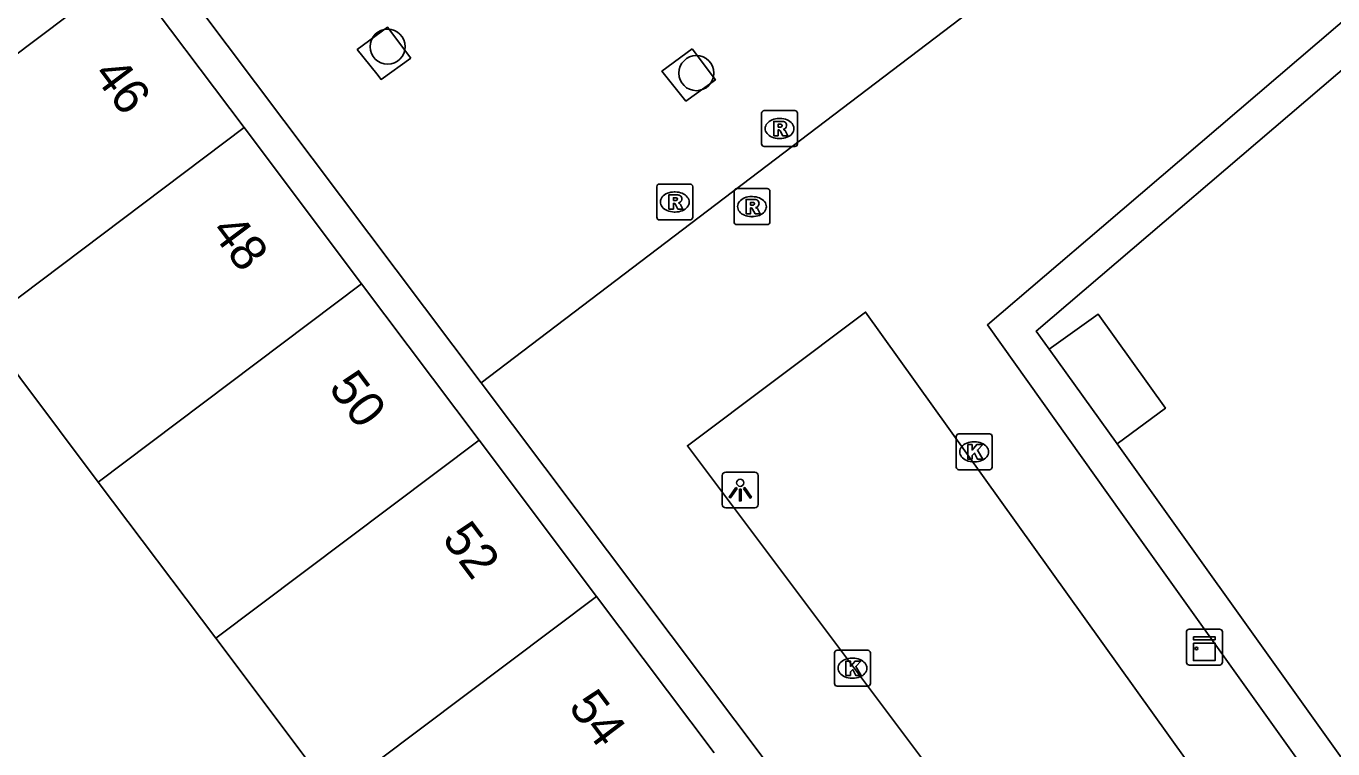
# Model space of a CAD drawing. Extents: x 160379 to 161131, y 383940 to 384849.
# Drawn here: x 160622.08 to 160658.49, y 384575.16 to 384595.29 of the extents above; entities that cross this region are included whole.
import ezdxf

# ---------------------------------------------------------------- set-up
doc = ezdxf.new("R2010")
doc.units = 0
for name, color, linetype in [('IMGEO_Boom', 7, 'Continuous'), ('IMGEO_Kast', 7, 'Continuous'), ('IMGEO_Kolk', 7, 'Continuous'), ('IMGEO_Lichtpunt', 7, 'Continuous'), ('IMGEO_Pand', 7, 'Continuous'), ('IMGEO_Pand_nummerreeks', 7, 'Continuous'), ('IMGEO_Pand_overbouw', 7, 'Continuous'), ('IMGEO_Rioolput', 7, 'Continuous'), ('IMGEO_Voetgangersgebied_open', 7, 'Continuous')]:
    doc.layers.add(name, color=color, linetype=linetype)

msp = doc.modelspace()

# ---------------------------------------------------------------- linework, layer by layer
at = {"layer": 'IMGEO_Boom'}
for centre in [(160632.154, 384594.722), (160640.758, 384593.985)]:
    msp.add_circle(centre, 0.489, dxfattribs=at)
at = {"layer": 'IMGEO_Kast'}
for p, q in [((160654.485, 384578.496), (160655.326, 384578.496)), ((160655.326, 384578.496), (160654.485, 384578.496)), ((160654.41, 384577.571), (160654.41, 384578.412)), ((160654.41, 384578.412), (160654.41, 384577.571)), ((160655.41, 384578.421), (160655.41, 384577.58)), ((160655.41, 384577.58), (160655.41, 384578.421)), ((160655.335, 384577.496), (160654.494, 384577.496)), ((160654.494, 384577.496), (160655.335, 384577.496))]:
    msp.add_line(p, q, dxfattribs=at)
for points in [[(160654.605, 384578.286), (160655.205, 384578.286), (160655.205, 384578.201), (160654.605, 384578.201), (160654.605, 384578.286)], [(160654.605, 384578.111), (160655.205, 384578.111), (160655.205, 384577.622), (160654.605, 384577.622), (160654.605, 384578.111)]]:
    msp.add_lwpolyline(points, dxfattribs=at)
msp.add_circle((160654.689, 384577.96), 0.0377, dxfattribs=at)
for centre, start, end in [((160654.488, 384578.418), 92.4484, 184.2845), ((160654.488, 384578.418), 92.4484, 184.2845), ((160655.332, 384578.418), 2.4484, 94.2845), ((160655.332, 384578.418), 2.4484, 94.2845), ((160654.488, 384577.574), 182.4484, 274.2845), ((160654.488, 384577.574), 182.4484, 274.2845), ((160655.332, 384577.574), 272.4484, 4.2845), ((160655.332, 384577.574), 272.4484, 4.2845)]:
    msp.add_arc(centre, 0.0779, start, end, dxfattribs=at)
at = {"layer": 'IMGEO_Kolk'}
for p, q in [((160647.995, 384583.011), (160647.995, 384583.863)), ((160648.07, 384583.937), (160648.922, 384583.937)), ((160648.483, 384583.717), (160648.508, 384583.717)), ((160648.996, 384583.863), (160648.996, 384583.011)), ((160648.922, 384582.937), (160648.07, 384582.937)), ((160648.506, 384583.157), (160648.481, 384583.157)), ((160644.604, 384576.984), (160644.604, 384577.836)), ((160644.679, 384577.91), (160645.531, 384577.91)), ((160645.605, 384577.836), (160645.605, 384576.984)), ((160645.092, 384577.69), (160645.117, 384577.69)), ((160645.115, 384577.13), (160645.09, 384577.13)), ((160645.531, 384576.91), (160644.679, 384576.91))]:
    msp.add_line(p, q, dxfattribs=at)
for points in [[(160647.995, 384583.011), (160647.995, 384583.863)], [(160648.07, 384583.937), (160648.922, 384583.937)], [(160648.316, 384583.637), (160648.439, 384583.637), (160648.439, 384583.486), (160648.569, 384583.637), (160648.733, 384583.637), (160648.587, 384583.486), (160648.74, 384583.237), (160648.588, 384583.237), (160648.503, 384583.401), (160648.439, 384583.334), (160648.439, 384583.237), (160648.316, 384583.237), (160648.316, 384583.637)], [(160648.996, 384583.863), (160648.996, 384583.011)], [(160648.922, 384582.937), (160648.07, 384582.937)], [(160644.604, 384576.984), (160644.604, 384577.836)], [(160644.679, 384577.91), (160645.531, 384577.91)], [(160645.605, 384577.836), (160645.605, 384576.984)], [(160644.925, 384577.61), (160645.048, 384577.61), (160645.048, 384577.459), (160645.178, 384577.61), (160645.342, 384577.61), (160645.196, 384577.459), (160645.349, 384577.21), (160645.197, 384577.21), (160645.112, 384577.374), (160645.048, 384577.307), (160645.048, 384577.21), (160644.925, 384577.21), (160644.925, 384577.61)], [(160645.531, 384576.91), (160644.679, 384576.91)]]:
    msp.add_lwpolyline(points, dxfattribs=at)
for centre, start, end in [((160648.072, 384583.861), 91.552, 178.448), ((160648.072, 384583.861), 91.552, 178.448), ((160648.92, 384583.861), 1.552, 88.448), ((160648.92, 384583.861), 1.552, 88.448), ((160648.072, 384583.013), 181.552, 268.448), ((160648.072, 384583.013), 181.552, 268.448), ((160648.92, 384583.013), 271.552, 358.448), ((160648.92, 384583.013), 271.552, 358.448), ((160644.681, 384577.834), 91.552, 178.448), ((160644.681, 384577.834), 91.552, 178.448), ((160645.529, 384577.834), 1.552, 88.448), ((160645.529, 384577.834), 1.552, 88.448), ((160644.681, 384576.986), 181.552, 268.448), ((160644.681, 384576.986), 181.552, 268.448), ((160645.529, 384576.986), 271.552, 358.448), ((160645.529, 384576.986), 271.552, 358.448)]:
    msp.add_arc(centre, 0.0765, start, end, dxfattribs=at)
for centre, major_axis, ratio, start_param, end_param in [((160648.482, 384583.437), (-0.387, 0.002), 0.722429, 4.712389, 7.853982), ((160648.507, 384583.437), (-0.39, 0.002), 0.717154, 1.570796, 4.712389), ((160645.091, 384577.41), (-0.387, 0.002), 0.722429, 4.712389, 7.853982), ((160645.116, 384577.41), (-0.39, 0.002), 0.717154, 1.570796, 4.712389)]:
    msp.add_ellipse(centre, major_axis=major_axis, ratio=ratio, start_param=start_param, end_param=end_param, dxfattribs=at)
at = {"layer": 'IMGEO_Lichtpunt'}
for p, q in [((160642.381, 384582.872), (160641.573, 384582.872)), ((160642.381, 384582.872), (160641.573, 384582.872)), ((160641.479, 384582.777), (160641.479, 384581.97)), ((160641.479, 384582.777), (160641.479, 384581.97)), ((160642.475, 384581.97), (160642.475, 384582.777)), ((160642.475, 384581.97), (160642.475, 384582.777)), ((160641.573, 384581.876), (160642.381, 384581.876)), ((160641.573, 384581.876), (160642.381, 384581.876))]:
    msp.add_line(p, q, dxfattribs=at)
for points in [[(160641.853, 384582.441), (160641.892, 384582.413), (160641.704, 384582.151), (160641.666, 384582.178), (160641.853, 384582.441)], [(160641.955, 384582.393), (160642.002, 384582.393), (160642.002, 384582.071), (160641.955, 384582.071), (160641.955, 384582.393)], [(160642.065, 384582.413), (160642.103, 384582.44), (160642.29, 384582.178), (160642.251, 384582.15), (160642.065, 384582.413)]]:
    msp.add_lwpolyline(points, dxfattribs=at)
msp.add_circle((160641.978, 384582.575), 0.0994, dxfattribs=at)
for centre, start, end in [((160641.573, 384582.777), 90, 180), ((160641.573, 384582.777), 90, 180), ((160642.381, 384582.777), 0, 90), ((160642.381, 384582.777), 0, 90), ((160641.573, 384581.97), 180, 270), ((160641.573, 384581.97), 180, 270), ((160642.381, 384581.97), 270, 0), ((160642.381, 384581.97), 270, 360)]:
    msp.add_arc(centre, 0.0946, start, end, dxfattribs=at)
at = {"layer": 'IMGEO_Pand'}
for points in [[(160663.725, 384567.919), (160652.479, 384583.658), (160653.822, 384584.649), (160651.953, 384587.271), (160650.586, 384586.297), (160650.225, 384586.801), (160659.075, 384594.356), (160663.636, 384598.249), (160664.714, 384596.986), (160667.165, 384599.079), (160666.087, 384600.341), (160670.751, 384604.318), (160692.141, 384590.55)], [(160624.884, 384596.822), (160617.544, 384591.3)], [(160624.884, 384596.822), (160628.157, 384592.469)], [(160628.157, 384592.469), (160620.818, 384586.948)], [(160628.157, 384592.469), (160631.431, 384588.116)], [(160631.431, 384588.116), (160624.091, 384582.595)], [(160631.431, 384588.116), (160634.704, 384583.762)], [(160624.091, 384582.595), (160620.818, 384586.948)], [(160634.704, 384583.762), (160627.365, 384578.243)], [(160634.704, 384583.762), (160637.977, 384579.409)], [(160627.365, 384578.243), (160624.091, 384582.595)], [(160637.977, 384579.409), (160630.639, 384573.89)], [(160637.977, 384579.409), (160641.25, 384575.056)], [(160630.639, 384573.89), (160627.365, 384578.243)]]:
    msp.add_lwpolyline(points, dxfattribs=at)
at = {"layer": 'IMGEO_Pand_overbouw'}
msp.add_lwpolyline([(160652.479, 384583.658), (160653.822, 384584.649), (160651.953, 384587.271), (160650.586, 384586.297)], close=True, dxfattribs=at)
at = {"layer": 'IMGEO_Rioolput'}
for p, q in [((160642.574, 384592.016), (160642.574, 384592.868)), ((160642.649, 384592.942), (160643.501, 384592.942)), ((160643.062, 384592.722), (160643.087, 384592.722)), ((160643.575, 384592.868), (160643.575, 384592.016)), ((160643.085, 384592.162), (160643.06, 384592.162)), ((160643.501, 384591.942), (160642.649, 384591.942)), ((160639.729, 384590.896), (160640.581, 384590.896)), ((160639.654, 384589.97), (160639.654, 384590.822)), ((160640.142, 384590.676), (160640.167, 384590.676)), ((160640.655, 384590.822), (160640.655, 384589.97)), ((160641.805, 384589.841), (160641.805, 384590.693)), ((160641.88, 384590.767), (160642.732, 384590.767)), ((160642.293, 384590.547), (160642.318, 384590.547)), ((160642.806, 384590.693), (160642.806, 384589.841)), ((160640.581, 384589.896), (160639.729, 384589.896)), ((160640.165, 384590.116), (160640.14, 384590.116)), ((160642.316, 384589.987), (160642.291, 384589.987)), ((160642.732, 384589.767), (160641.88, 384589.767))]:
    msp.add_line(p, q, dxfattribs=at)
for points in [[(160642.574, 384592.016), (160642.574, 384592.868)], [(160642.649, 384592.942), (160643.501, 384592.942)], [(160643.575, 384592.868), (160643.575, 384592.016)], [(160643.163, 384592.64), (160642.911, 384592.642), (160642.911, 384592.242)], [(160642.911, 384592.242), (160643.035, 384592.242), (160643.035, 384592.404), (160643.046, 384592.404)], [(160643.089, 384592.561), (160643.035, 384592.561), (160643.035, 384592.48)], [(160643.035, 384592.48), (160643.087, 384592.48)], [(160643.093, 384592.375), (160643.164, 384592.242), (160643.304, 384592.242), (160643.239, 384592.368)], [(160643.501, 384591.942), (160642.649, 384591.942)], [(160639.729, 384590.896), (160640.581, 384590.896)], [(160639.654, 384589.97), (160639.654, 384590.822)], [(160640.243, 384590.594), (160639.991, 384590.596), (160639.991, 384590.196)], [(160640.169, 384590.515), (160640.115, 384590.515), (160640.115, 384590.434)], [(160640.655, 384590.822), (160640.655, 384589.97)], [(160641.805, 384589.841), (160641.805, 384590.693)], [(160641.88, 384590.767), (160642.732, 384590.767)], [(160642.806, 384590.693), (160642.806, 384589.841)], [(160639.991, 384590.196), (160640.115, 384590.196), (160640.115, 384590.358), (160640.126, 384590.358)], [(160640.115, 384590.434), (160640.167, 384590.434)], [(160640.173, 384590.329), (160640.244, 384590.196), (160640.384, 384590.196), (160640.319, 384590.322)], [(160642.394, 384590.465), (160642.142, 384590.467), (160642.142, 384590.067)], [(160642.142, 384590.067), (160642.266, 384590.067), (160642.266, 384590.229), (160642.277, 384590.229)], [(160642.32, 384590.386), (160642.266, 384590.386), (160642.266, 384590.305)], [(160642.266, 384590.305), (160642.318, 384590.305)], [(160642.324, 384590.2), (160642.395, 384590.067), (160642.535, 384590.067), (160642.47, 384590.193)], [(160640.581, 384589.896), (160639.729, 384589.896)], [(160642.732, 384589.767), (160641.88, 384589.767)]]:
    msp.add_lwpolyline(points, dxfattribs=at)
for centre, radius, start, end in [((160642.651, 384592.866), 0.0765, 91.552, 178.448), ((160642.651, 384592.866), 0.0765, 91.552, 178.448), ((160643.499, 384592.866), 0.0765, 1.552, 88.448), ((160643.499, 384592.866), 0.0765, 1.552, 88.448), ((160643.045, 384592.351), 0.0533, 26.0293, 88.6989), ((160643.071, 384592.669), 0.19, 274.7715, 282.9687), ((160643.095, 384592.465), 0.0964, 77.0061, 93.1865), ((160643.109, 384592.522), 0.0378, 276.6634, 79.6772), ((160643.162, 384592.53), 0.109, 350.3612, 89.416), ((160643.16, 384592.53), 0.112, 277.5842, 350.9817), ((160643.144, 384592.315), 0.108, 29.5134, 73.7905), ((160642.651, 384592.018), 0.0765, 181.552, 268.448), ((160642.651, 384592.018), 0.0765, 181.552, 268.448), ((160643.499, 384592.018), 0.0765, 271.552, 358.448), ((160643.499, 384592.018), 0.0765, 271.552, 358.448), ((160639.731, 384590.82), 0.0765, 91.552, 178.448), ((160639.731, 384590.82), 0.0765, 91.552, 178.448), ((160640.579, 384590.82), 0.0765, 1.552, 88.448), ((160640.579, 384590.82), 0.0765, 1.552, 88.448), ((160640.175, 384590.419), 0.0964, 77.0061, 93.1865), ((160640.189, 384590.476), 0.0378, 276.6634, 79.6772), ((160640.242, 384590.484), 0.109, 350.3612, 89.416), ((160641.882, 384590.691), 0.0765, 91.552, 178.448), ((160641.882, 384590.691), 0.0765, 91.552, 178.448), ((160642.73, 384590.691), 0.0765, 1.552, 88.448), ((160642.73, 384590.691), 0.0765, 1.552, 88.448), ((160640.125, 384590.305), 0.0533, 26.0293, 88.6989), ((160640.151, 384590.623), 0.19, 274.7715, 282.9687), ((160640.24, 384590.484), 0.112, 277.5842, 350.9817), ((160640.224, 384590.269), 0.108, 29.5134, 73.7905), ((160642.276, 384590.176), 0.0533, 26.0293, 88.6989), ((160642.302, 384590.494), 0.19, 274.7715, 282.9687), ((160642.326, 384590.29), 0.0964, 77.0061, 93.1865), ((160642.34, 384590.347), 0.0378, 276.6634, 79.6772), ((160642.393, 384590.355), 0.109, 350.3612, 89.416), ((160642.391, 384590.355), 0.112, 277.5842, 350.9817), ((160642.375, 384590.14), 0.108, 29.5134, 73.7905), ((160639.731, 384589.972), 0.0765, 181.552, 268.448), ((160639.731, 384589.972), 0.0765, 181.552, 268.448), ((160640.579, 384589.972), 0.0765, 271.552, 358.448), ((160640.579, 384589.972), 0.0765, 271.552, 358.448), ((160641.882, 384589.843), 0.0765, 181.552, 268.448), ((160641.882, 384589.843), 0.0765, 181.552, 268.448), ((160642.73, 384589.843), 0.0765, 271.552, 358.448), ((160642.73, 384589.843), 0.0765, 271.552, 358.448)]:
    msp.add_arc(centre, radius, start, end, dxfattribs=at)
for centre, major_axis, ratio, start_param, end_param in [((160643.061, 384592.442), (-0.387, 0.002), 0.722429, 4.712389, 7.853982), ((160643.086, 384592.442), (-0.39, 0.002), 0.717154, 1.570796, 4.712389), ((160640.141, 384590.396), (-0.387, 0.002), 0.722429, 4.712389, 7.853982), ((160640.166, 384590.396), (-0.39, 0.002), 0.717154, 1.570796, 4.712389), ((160642.292, 384590.267), (-0.387, 0.002), 0.722429, 4.712389, 7.853982), ((160642.317, 384590.267), (-0.39, 0.002), 0.717154, 1.570796, 4.712389)]:
    msp.add_ellipse(centre, major_axis=major_axis, ratio=ratio, start_param=start_param, end_param=end_param, dxfattribs=at)
at = {"layer": 'IMGEO_Voetgangersgebied_open'}
for points in [[(160608.482, 384613.028), (160611.972, 384615.646), (160634.758, 384585.358)], [(160682.984, 384507.279), (160681.057, 384517.15), (160670.583, 384546.086), (160670.064, 384547.52), (160665.29, 384560.709), (160662.829, 384567.417), (160652.625, 384581.692), (160648.865, 384586.974), (160652.047, 384589.687), (160670.645, 384605.594)], [(160634.758, 384585.358), (160653.945, 384599.94)], [(160632.8, 384594.402), (160631.975, 384593.808), (160631.851, 384593.964), (160631.308, 384594.641), (160632.149, 384595.267), (160632.8, 384594.402)], [(160640.637, 384594.665), (160641.288, 384593.8), (160640.464, 384593.207), (160639.797, 384594.039), (160640.637, 384594.665)], [(160650.122, 384570.791), (160640.506, 384583.605), (160645.47, 384587.329), (160658.158, 384569.619)], [(160656.893, 384504.376), (160651.516, 384563.083), (160634.758, 384585.358)]]:
    msp.add_lwpolyline(points, dxfattribs=at)

# ---------------------------------------------------------------- texts
at = {"layer": 'IMGEO_Pand_nummerreeks'}
for s, p in [('46', (160623.925, 384593.939)), ('48', (160627.203, 384589.579)), ('50', (160630.487, 384585.212)), ('52', (160633.648, 384581.008)), ('54', (160637.168, 384576.326))]:
    msp.add_text(s, height=1, rotation=306.9384, dxfattribs=at).set_placement(p)

doc.saveas('drawing.dxf')
